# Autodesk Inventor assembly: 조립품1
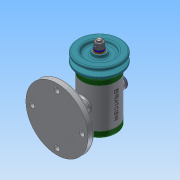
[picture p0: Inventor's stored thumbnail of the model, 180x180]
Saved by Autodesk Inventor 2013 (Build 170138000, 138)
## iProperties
Created: 2018-12
Part Number: 조립품1
Document SubType Name: Assembly
Designer: Administrator
Author: Administrator
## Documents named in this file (15)
- C:\Users\Administrator\Desktop\시험\481207V1045\조립품1.iam
- C:\Users\Administrator\Desktop\시험\481207V1045\본체.ipt
- C:\Users\Administrator\Desktop\시험\481207V1045\축.ipt
- C:\Users\Administrator\Desktop\시험\481207V1045\뒤커버.ipt
- C:\Users\Administrator\Desktop\시험\481207V1045\베어링 15 x 32 x 9.ipt
- C:\Users\Administrator\Desktop\시험\481207V1045\키 3 x 3 x 12.ipt
- C:\Users\Administrator\Desktop\시험\481207V1045\앞커버.ipt
- C:\Users\Administrator\Desktop\시험\481207V1045\오일 실 15 25 7.ipt
- C:\Users\Administrator\Desktop\시험\481207V1045\볼트 M4 x 12.ipt
- C:\Users\Administrator\Desktop\시험\481207V1045\너트 M8.ipt
- 너트 M8.ipt
- C:\Users\Administrator\Desktop\시험\481207V1045\스프링와셔 8.ipt
- C:\Users\Administrator\Desktop\시험\481207V1045\와셔 8x17.ipt
- C:\Users\Administrator\Desktop\시험\481207V1045\V벨트풀리.ipt
- C:\Users\Administrator\Desktop\시험\481207V1045\고무캡.ipt
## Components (2 placed, 2 different names)
1. V벨트풀리:1
2. 고무캡:1
